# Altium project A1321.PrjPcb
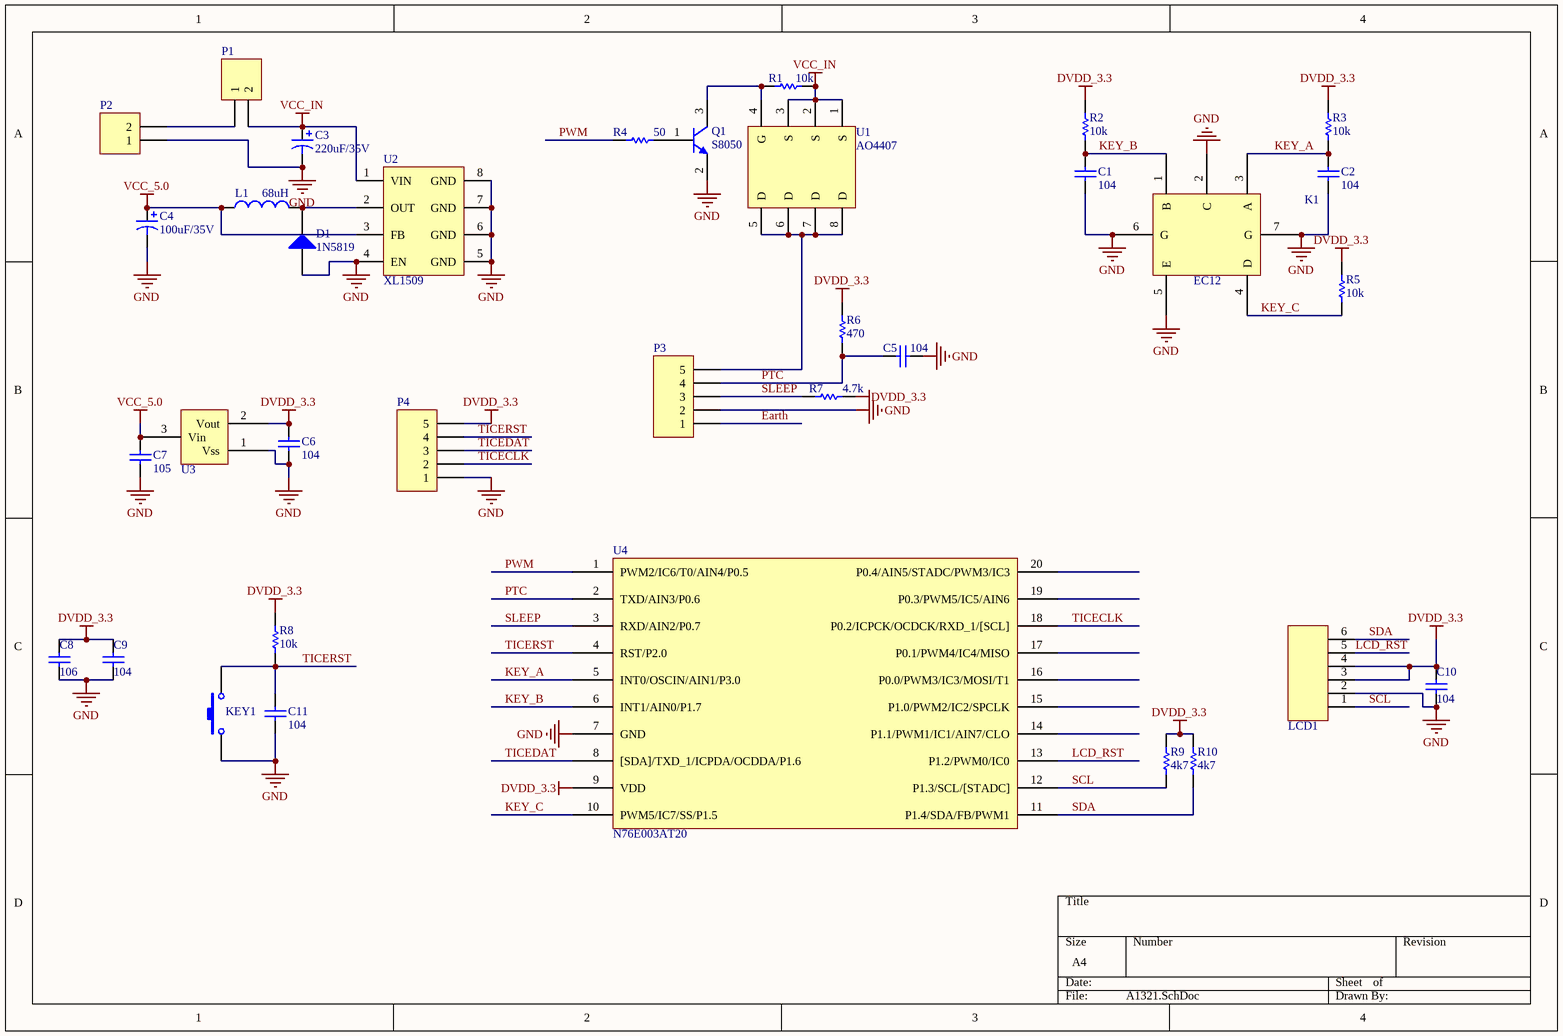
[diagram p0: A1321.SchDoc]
1 sheet, 35 parts. Net scope: global (net labels, ports and power ports of the same name join across sheets).
Board file: A1321.PcbDoc

## Sheet A1321.SchDoc
size A4

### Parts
C1  C0603  [C0603]  (value not drawn)
C2  C0603  [C0603]  (value not drawn)
C3  Capacitor  [C6.3*6.3]  (value not drawn)
C4  Capacitor  [C6.3*6.3]  (value not drawn)
C5  C0603  [C0603]  (value not drawn)
C6  C0603  [C0603]  (value not drawn)
C7  C0603  [C0603]  (value not drawn)
C8  C0603  [C0603]  (value not drawn)
C9  C0603  [C0603]  (value not drawn)
C10  C0603  [C0603]  (value not drawn)
C11  C0603  [C0603]  (value not drawn)
D1  1N5819  [SOD323]
K1  EC12  [EC12]
KEY1  KEY  [KEY_SMD]  (value not drawn)
L1  CD32  [CD32]  (value not drawn)
LCD1  FPC6PIN-0.5  [FPC6PIN-0.5]  (value not drawn)
P1  (no value)  [HDR1X2]
P2  (no value)  [HDR1X2]
P3  (no value)  [HDR1X5]
P4  (no value)  [HDR1X5]
Q1  S8050  [SOT23]
R1  R0805  [R0805]  (value not drawn)
R2  R0603  [R0603]  (value not drawn)
R3  R0603  [R0603]  (value not drawn)
R4  R0603  [R0603]  (value not drawn)
R5  R0603  [R0603]  (value not drawn)
R6  R0603  [R0603]  (value not drawn)
R7  R0603  [R0603]  (value not drawn)
R8  R0603  [R0603]  (value not drawn)
R9  R0603  [R0603]  (value not drawn)
R10  R0603  [R0603]  (value not drawn)
U1  AO4407  [SOP8]
U2  XL1509  [SOP8]
U3  XC6206P332MR  [SOT23]  (value not drawn)
U4  N76E003AT20  [N76E003AT20]

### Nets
DVDD_3.3: C6.2 C8.2 C9.2 C10.2 LCD1.3 LCD1.4 P4.5 R2.2 R3.2 R5.2 R6.2 R7.1 R8.2 R9.2 R10.2 U3.2(Vout) U4.9(VDD)
GND: C1.1 C2.1 C3.2 C4.2 C5.1 C6.1 C7.1 C8.1 C9.1 C10.1 C11.1 D1.1(A) K1.2(C) K1.5(E) K1.6(G) K1.7(G) KEY1.1 LCD1.2 P2.1 P3.2 P4.1 Q1.2(E) U2.4(EN) U2.5(GND) U2.6(GND) U2.7(GND) U2.8(GND) U3.1(Vss) U4.7(GND)
VCC_5.0: C4.1 C7.2 L1.1 U2.3(FB) U3.3(Vin)
VCC_IN: C3.1 P1.2 R1.1 U1.1(S) U1.2(S) U1.3(S) U2.1(VIN)
Earth: P3.1
KEY_A: C2.2 K1.3(A) R3.1 U4.5(INT0/OSCIN/AIN1/P3.0)
KEY_B: C1.2 K1.1(B) R2.1 U4.6(INT1/AIN0/P1.7)
KEY_C: K1.4(D) R5.1 U4.10(PWM5/IC7/SS/P1.5)
LCD_RST: LCD1.5 U4.13(P1.2/PWM0/IC0)
PTC: C5.2 P3.4 R6.1 U4.2(TXD/AIN3/P0.6)
PWM: R4.1 U4.1(PWM2/IC6/T0/AIN4/P0.5)
SCL: LCD1.1 R9.1 U4.12(P1.3/SCL/[STADC])
SDA: LCD1.6 R10.1 U4.11(P1.4/SDA/FB/PWM1)
SLEEP: P3.3 R7.2 U4.3(RXD/AIN2/P0.7)
TICECLK: P4.2 U4.18(P0.2/ICPCK/OCDCK/RXD_1/[SCL])
TICEDAT: P4.3 U4.8([SDA]/TXD_1/ICPDA/OCDDA/P1.6)
TICERST: C11.2 KEY1.2 P4.4 R8.1 U4.4(RST/P2.0)
NetD1_2: D1.2(K) L1.2 U2.2(OUT)
NetP1_1: P1.1 P2.2
NetP3_5: P3.5 U1.5(D) U1.6(D) U1.7(D) U1.8(D)
NetQ1_1: Q1.1(B) R4.2
NetQ1_3: Q1.3(C) R1.2 U1.4(G)

Not connected (* = marked no-connect by the designer): U4 14(P1.1/PWM1/IC1/AIN7/CLO) 15(P1.0/PWM2/IC2/SPCLK) 16(P0.0/PWM3/IC3/MOSI/T1) 17(P0.1/PWM4/IC4/MISO) 19(P0.3/PWM5/IC5/AIN6) 20(P0.4/AIN5/STADC/PWM3/IC3)

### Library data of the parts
C3 C4 = C6.3*6.3
D1 = 1N5825
P1 P2 = Header 2: Header, 2-Pin
P3 P4 = Header 5: Header, 5-Pin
